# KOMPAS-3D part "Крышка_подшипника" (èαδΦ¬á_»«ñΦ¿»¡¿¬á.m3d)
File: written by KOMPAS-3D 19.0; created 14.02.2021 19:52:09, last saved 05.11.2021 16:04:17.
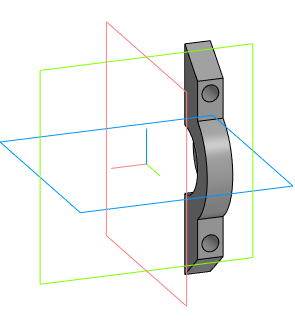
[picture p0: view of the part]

Document properties: Автор: Agent Smith; Полное имя файла: D:\3D_print\3D проекты Компас 3D\Халява Projects 5\Крышка_подшипника.m3d

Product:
- Part/product: Крышка_подшипника
    Масса: 0.0173967

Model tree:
1. Эскиз:1  (with: Элемент выдавливания:9, Элемент выдавливания:1)
2. Элемент выдавливания:1  (with: Элемент выдавливания:9)
     Расстояние 2 = 6
3. Эскиз:2  (with: Элемент выдавливания:1, Элемент выдавливания:13)
4. Элемент выдавливания:2  (with: Элемент выдавливания:9)
     Расстояние 2 = 8
5. Эскиз:3  (with: Элемент выдавливания:1)
6. Элемент выдавливания:3  (with: Элемент выдавливания:1)
     Расстояние 1 = 1

Referenced files in D:\3D_print\3D проекты Компас 3D\Редуктор (Снова)\: Намоточный станок (Projects 6).a3d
